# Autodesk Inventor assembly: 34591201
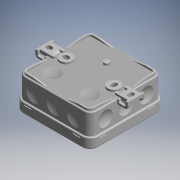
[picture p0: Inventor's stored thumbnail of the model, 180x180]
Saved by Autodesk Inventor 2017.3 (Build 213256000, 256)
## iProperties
Category: PARTsolutions
Company: SPELSBERG
Part Number: 34591201
Catalog Web Link: www.cadenas.de
Description: IP 55 - for rapid installation with self sealing membrane  Assemblies-
Vendor: SPELSBERG
Document SubType Name: Assembly
Designer: partserver
Manufacturer: SPELSBERG
Mass: 48.7748 g
Surface Area: 622.682 cm^2
Volume: 48.7748 cm^3
Density: 1 g/cm^3
Title: 34591201
Author: Cadenas PARTsolutions
PSOL_IDENT_0: {$CADENAS_DATA\23d-libs\spelsberg\24me02-15461449\24me03-15461517\24me04-100005011220asm.prj},246 {V
PSOL_IDENT_1: TYP=3D},{STYP=ASSTAB},{NB=34591201},{LINA=34591201},{NN=IP 55 - for rapid installation with self sea
PSOL_IDENT_2: ling membrane  Assemblies},{DATE=27.03.2020 09:09:55},{GEOMDATE=10.03.2020 08:58:48},{VERSION=v20031
PSOL_IDENT_3: 0085848},{LINEID=90},{WBVAR=},{WBNUMERIC=}  {NB=34591201},{LINA=34591201},{KT=DUMMY},{MD01=../../_po
PSOL_IDENT_4: ol_/df/b9/pho_pro_34591201_sall_acadenas_v1.png},{DESCSHORT=2K-12 AB-L},{DESCLONG=Junction box acc.
PSOL_IDENT_5: to DIN EN 60670 (VDE 0606), 12 entries, 2 floor entries, with self-sealing, soft inlet membranes, to
PSOL_IDENT_6: ols not required for opening the cable entry, seal range 2 - 14 mm, with external fixing lugs, Grey,
PSOL_IDENT_7: without terminals, for VDE approved single terminals},{EAN=1000127286},{MANUID=34591201},{MANUNAME=
PSOL_IDENT_8: Spelsberg},{MANUTYPEDESC=2K-12 AB-L},{EF000003=Wall-/ceiling mounting},{EF000007=Other},{EF000008=85
PSOL_IDENT_9: },{EF000025=true},{EF000049=85},{EF000051=Rectangular},{EF000139=Untreated},{EF000551=-},{EF000557=C
PSOL_IDENT_10: lamp},{EF001366=400},{EF001438=37},{EF001454=false},{EF001613=None},{EF001742=25 - 40},{EF002169=Pla
PSOL_IDENT_11: stic},{EF003593=12},{EF004191=false},{EF004586=Snapped on},{EF004969=2.5},{EF005032=false},{EF005436=
PSOL_IDENT_12: true},{EF005474=IP55},{EF005496=-},{EF005604=true},{EF005728=None},{EF006169=false},{EF007661=Seal m
PSOL_IDENT_13: embrane},{EF008404=None},{EF009212=Mounting cover},{EF009476=true},{EF009477=false},{EF011401=false}
PSOL_IDENT_14: ,{EF011959=-},{EF012570=false},{EF012571=false},{PRICEQUANTITY=1},{WEIGHT=0.0460},{LENGTH=85},{WIDTH=
PSOL_IDENT_15: 85},{DEPTH=37},{COO=DE},{CTC=8538 90 99},{MD04=MD04},{MD04_=https://www.spelsberg.com/p/34591201},{M
PSOL_IDENT_16: D04_ENG=https://www.spelsberg.com/p/34591201},{MD04_DEU=https://www.spelsberg.de/p/34591201},{PPATH=
PSOL_IDENT_17: ../../pool/verbindungsdosen/assemblies/34591201_asmtpl.prj}
NB: 34591201
NN: IP 55 - for rapid installation with self sealing membrane  Assemblies
NBSYN: $MANUID.
LINA: 34591201
CATALOG: Spelsberg
MD01: ../../_pool_/df/b9/pho_pro_34591201_sall_acadenas_v1.png
DESCSHORT: 2K-12 AB-L
DESCLONG: Junction box acc. to DIN EN 60670 (VDE 0606), 12 entries, 2 floor entries, with self-sealing, soft inlet membranes, tools not required for opening the cable ent
EAN: 1000127286
MANUID: 34591201
MANUNAME: Spelsberg
MANUTYPEDESC: 2K-12 AB-L
EF000003: Wall-/ceiling mounting
EF000007: Other
EF000008: 85
EF000025: true
EF000049: 85
EF000051: Rectangular
EF000139: Untreated
EF000551: -
EF000557: Clamp
EF001366: 400
EF001438: 37
EF001454: false
EF001742: 25 - 40
EF002169: Plastic
EF003593: 12
EF004191: false
EF004586: Snapped on
EF004969: 2.5
EF005032: false
EF005436: true
EF005474: IP55
EF005496: -
EF005604: true
EF006169: false
EF007661: Seal membrane
EF009212: Mounting cover
EF009476: true
EF009477: false
EF011401: false
EF011959: -
EF012570: false
EF012571: false
PRICEQUANTITY: 1
WEIGHT: 0.046
LENGTH: 85
WIDTH: 85
DEPTH: 37
COO: DE
CTC: 8538 90 99
MD04: MD04
SUPPLIER: SPELSBERG
ARTICLENO: 34591201
BOMINFO: 34591201
CREATOR: CADENAS GmbH
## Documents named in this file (3)
- e:\temp\worker_23\temp\exporttempdir_8200_184_hgUkW\format_0\34591201.iam
- e:\temp\worker_23\temp\exporttempdir_8200_184_hgUkW\format_0\Kasten_2k-12ab.ipt
- e:\temp\worker_23\temp\exporttempdir_8200_184_hgUkW\format_0\Deckel_2k-12.ipt
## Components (2 placed, 2 different names)
1. Kasten_2k-12ab:1 — KASTEN_XY@1 <-> DECKEL_XY@2, KASTEN_Z@1 <-> DECKEL_Z@2, KASTEN_YZ@1 <-> DECKEL_YZ@2
2. Deckel_2k-12:1 — KASTEN_XY@1 <-> DECKEL_XY@2, KASTEN_Z@1 <-> DECKEL_Z@2, KASTEN_YZ@1 <-> DECKEL_YZ@2
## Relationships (3: Mate 2, Angle 1)
- KASTEN_XY@1 <-> DECKEL_XY@2 [Mate]: Kasten_2k-12ab:1 ↔ Deckel_2k-12:1
- KASTEN_Z@1 <-> DECKEL_Z@2 [Mate]: Kasten_2k-12ab:1 ↔ Deckel_2k-12:1
- KASTEN_YZ@1 <-> DECKEL_YZ@2 [Angle]: Kasten_2k-12ab:1 ↔ Deckel_2k-12:1
